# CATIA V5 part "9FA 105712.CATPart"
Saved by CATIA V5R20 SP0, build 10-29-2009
Part number: 9FA 105712
Revision: ANY
Definition: UNKNOWN
Nomenclature: 9FA 105712
Source: Unknown
Bounding box of the stored display mesh (mm): x -5 to 5, y -10 to 10, z -5 to 5
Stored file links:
  C:\Users\Utente\Desktop\IO LAVORO\3D X SITO CF\CUMSA\3D files FA\FA 1057SF\9FA 105712.CATPart

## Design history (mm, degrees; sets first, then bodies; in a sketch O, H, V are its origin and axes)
Set1 "FacciaKO#NONE#708"
  DatumSurface1 "Sup708_1"
  DatumCurve1 "Crv708_1"
Body1 "Cortar-Extruir5" (main body)
  Solid1: solid without history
